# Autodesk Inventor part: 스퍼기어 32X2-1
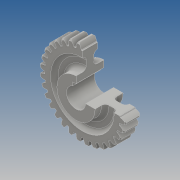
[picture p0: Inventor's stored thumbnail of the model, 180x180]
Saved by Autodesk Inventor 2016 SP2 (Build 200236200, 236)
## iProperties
Created: 2018-07
Part Number: 스퍼기어 32X2-1
Material: Generic
Document SubType Name: Modeling
Designer: Administrator
Density: 1 g/cm^3
Appearance: Default
Author: Administrator
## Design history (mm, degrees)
sketch "스케치1"
  geometry: L1 (-11, 0)-(11, 0); L2 (-11, 0)-(-11, 7.5); L3 (-11, 15)-(-3, 15); L4 (-3, 15)-(-3, 25); L5 (-3, 25)-(-6, 25); L6 (-6, 25)-(-6, 34); L7 (-6, 34)-(6, 34); L8 (6, 34)-(6, 25); L9 (6, 25)-(3, 25); L10 (3, 25)-(3, 15); L11 (3, 15)-(11, 15); L12 (11, 15)-(11, 7.5); L13 (-11, 7.5)-(11, 7.5); L14 (-11, 7.5)-(-11, 15); L15 (11, 7.5)-(11, 0); 3 further points
  constraints: 30 end point, 10 perpendicular, 4 point on line, 2 horizontal, 2 midpoint, 2 vertical, 1 coincident, 1 collinear, 1 vertical alignment
  dimensions: "d0" = 22 distance of L1.start L1.end; "d1" = 15 distance of L1.start L3.start; "d2" = 12 distance of L6.end L7.end; "d3" = 6 distance between parallel lines of L4 L10; "d4" = 50 diameter of L9 L1; "d5" = 68 diameter of L7 L1; "d6" = 15 diameter of L13 L1
revolve "회전1" sketch "스케치1" stored, may be unused: angle "d7" = 90 deg
sketch "스케치3"
  geometry: L1 (-2.5, 9.8)-(2.5, 9.8); L2 (2.5, 9.8)-(2.5, 7.071); L3 (-2.5, 7.071)-(-2.5, 9.8); A1 r 7.5 centre (0, 0) between (2.5, 7.071) and (-2.5, 7.071) reference
  constraints: 6 end point, 2 parallel, 2 point on circle, 1 horizontal, 1 perpendicular
  dimensions: "d23" = 5 distance of L1.start L1.end; "d24" = 2.3 distance edge to line of A1 L1
extrude "돌출2" cut sketch "스케치3" stored distance "d25" = 12; taper "d26" = 0 deg
sketch "스케치4"
  geometry: L1 (0, 0)-(3.349, 33.835); L2 (2.338, 29.407)-(2.781, 33.886); L3 (1.339, 29.47)-(1.585, 31.961); L4 (0.838, 29.488)-(1.085, 31.982); L5 (0, 0)-(0, 34); A1 r 34 centre (0, 0) between (3.349, 33.835) and (0, 34) reference; A2 r 34 centre (0, 0) between (3.349, 33.835) and (0, 34) reference; A3 r 32 centre (0, 0) between (1.085, 31.982) and (1.585, 31.961); A4 r 9.275 centre (10.004, 28.068) between (2.781, 33.886) and (0.838, 29.488); A5 r 9.275 centre (-10.004, 28.068) between (-0.838, 29.488) and (-2.781, 33.886); A6 r 29.5 centre (0, 0) between (0.838, 29.488) and (-0.838, 29.488); A7 r 34 centre (0, 0) between (2.781, 33.886) and (-2.781, 33.886)
  constraints: 16 point on circle, 10 end point, 5 centre point, 4 coincident, 3 parallel, 3 symmetric about line, 1 vertical, 1 other
  dimensions: "d30" = 64 diameter of A3; "d36" = 1.57 distance between parallel lines of L3 L1; "d37" = 1 distance between parallel lines of L3 L2; "d38" = 0.5 distance between parallel lines of L4 L3; "d39" = 5.652 deg angle of L5 L1
extrude "돌출3" cut sketch "스케치4" stored distance "d40" = 12; taper "d41" = 0 deg
chamfer "모따기4" distance "d55" = 1; stored, may be unused: second distance "d56" = 2, angle "d57" = 45 deg
fillet "모깎기4" dims "d58" = 0.5
fillet "모깎기5" dims "d62" = 3
sketch "스케치5"
  geometry: L1 (0, 0)-(52.329, 0); L2 (52.329, 0)-(52.329, 46.256); L3 (52.329, 46.256)-(0, 46.256); L4 (0, 46.256)-(0, 0); C1 r 15 at (0, 0) reference
  constraints: 8 end point, 2 parallel, 1 horizontal, 1 perpendicular
extrude "돌출4" cut sketch "스케치5" stored distance "d63" = 0; taper "d64" = 0 deg
node "솔리드1"
pattern_circular "원형 패턴4" dims angle "d60" = 360 deg
other parameters: "d27" = 1.57, "d28" = 1, "d29" = 0.5, "d33" = 1.57, "d34" = 1, "d35" = 0.5
